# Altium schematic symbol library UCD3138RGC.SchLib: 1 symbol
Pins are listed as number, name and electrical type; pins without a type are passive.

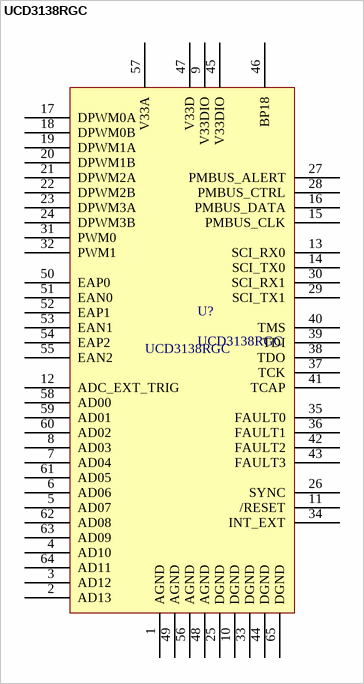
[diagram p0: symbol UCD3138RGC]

## UCD3138RGC
designator U?
pins: 1 AGND, 2 AD13, 3 AD12, 4 AD10, 5 AD07, 6 AD06, 7 AD04, 8 AD03, 9 V33DIO, 10 DGND, 11 /RESET, 12 ADC_EXT_TRIG, 13 SCI_RX0, 14 SCI_TX0, 15 PMBUS_CLK, 16 PMBUS_DATA, 17 DPWM0A, 18 DPWM0B, 19 DPWM1A, 20 DPWM1B, 21 DPWM2A, 22 DPWM2B, 23 DPWM3A, 24 DPWM3B, 25 DGND, 26 SYNC, 27 PMBUS_ALERT, 28 PMBUS_CTRL, 29 SCI_TX1, 30 SCI_RX1, 31 PWM0, 32 PWM1, 33 DGND, 34 INT_EXT, 35 FAULT0, 36 FAULT1, 37 TCK, 38 TDO, 39 TDI, 40 TMS, 41 TCAP, 42 FAULT2, 43 FAULT3, 44 DGND, 45 V33DIO, 46 BP18, 47 V33D, 48 AGND, 49 AGND, 50 EAP0, 51 EAN0, 52 EAP1, 53 EAN1, 54 EAP2, 55 EAN2, 56 AGND, 57 V33A, 58 AD00, 59 AD01, 60 AD02, 61 AD05, 62 AD08, 63 AD09, 64 AD11, 65 DGND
